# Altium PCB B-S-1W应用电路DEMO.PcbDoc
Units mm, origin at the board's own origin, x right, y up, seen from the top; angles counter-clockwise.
Board outline 40 x 15.24 mm, 2 copper layers (Top Layer, Bottom Layer); 6 components, 5 nets, 18 pads, 0 vias.
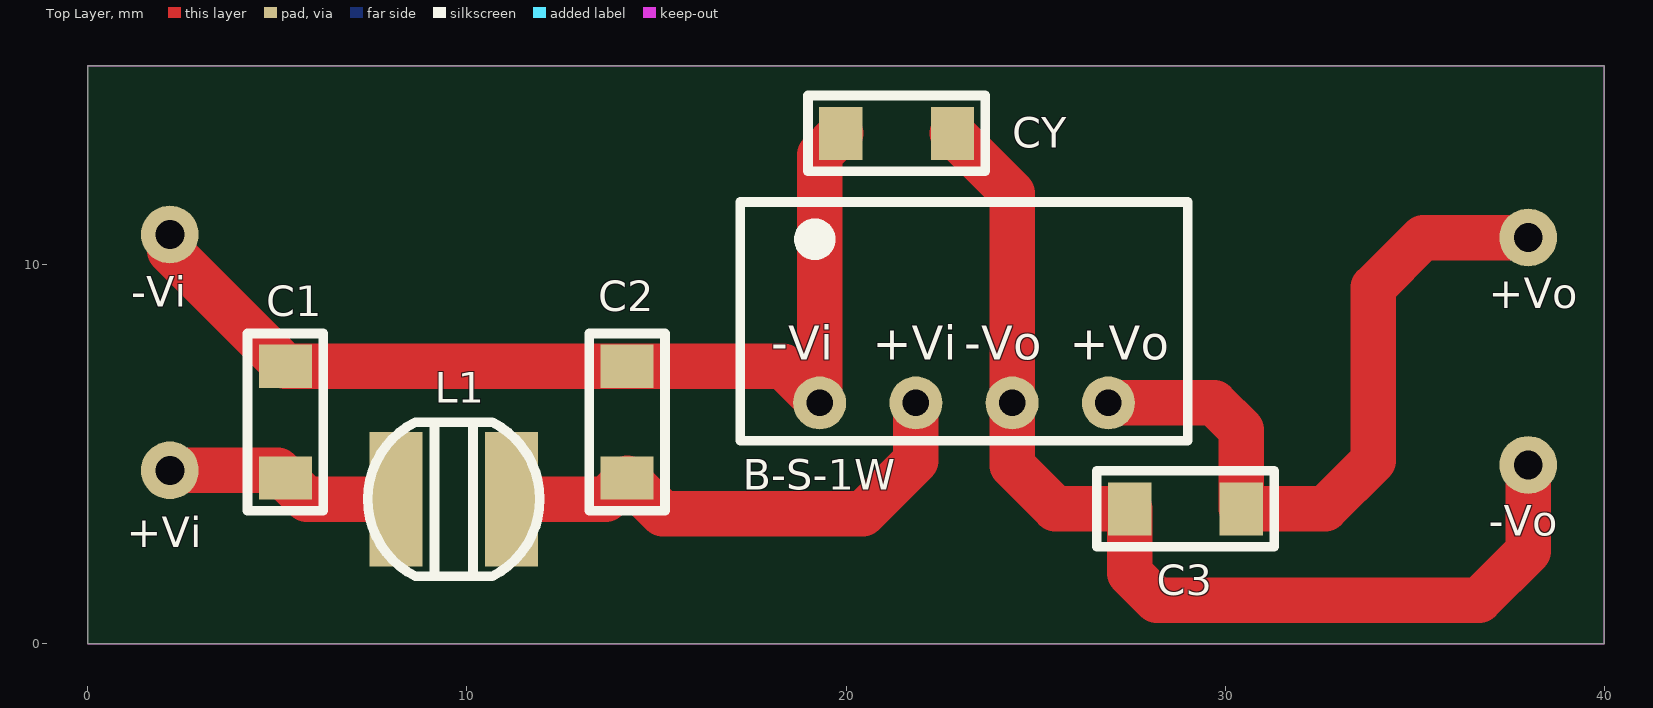
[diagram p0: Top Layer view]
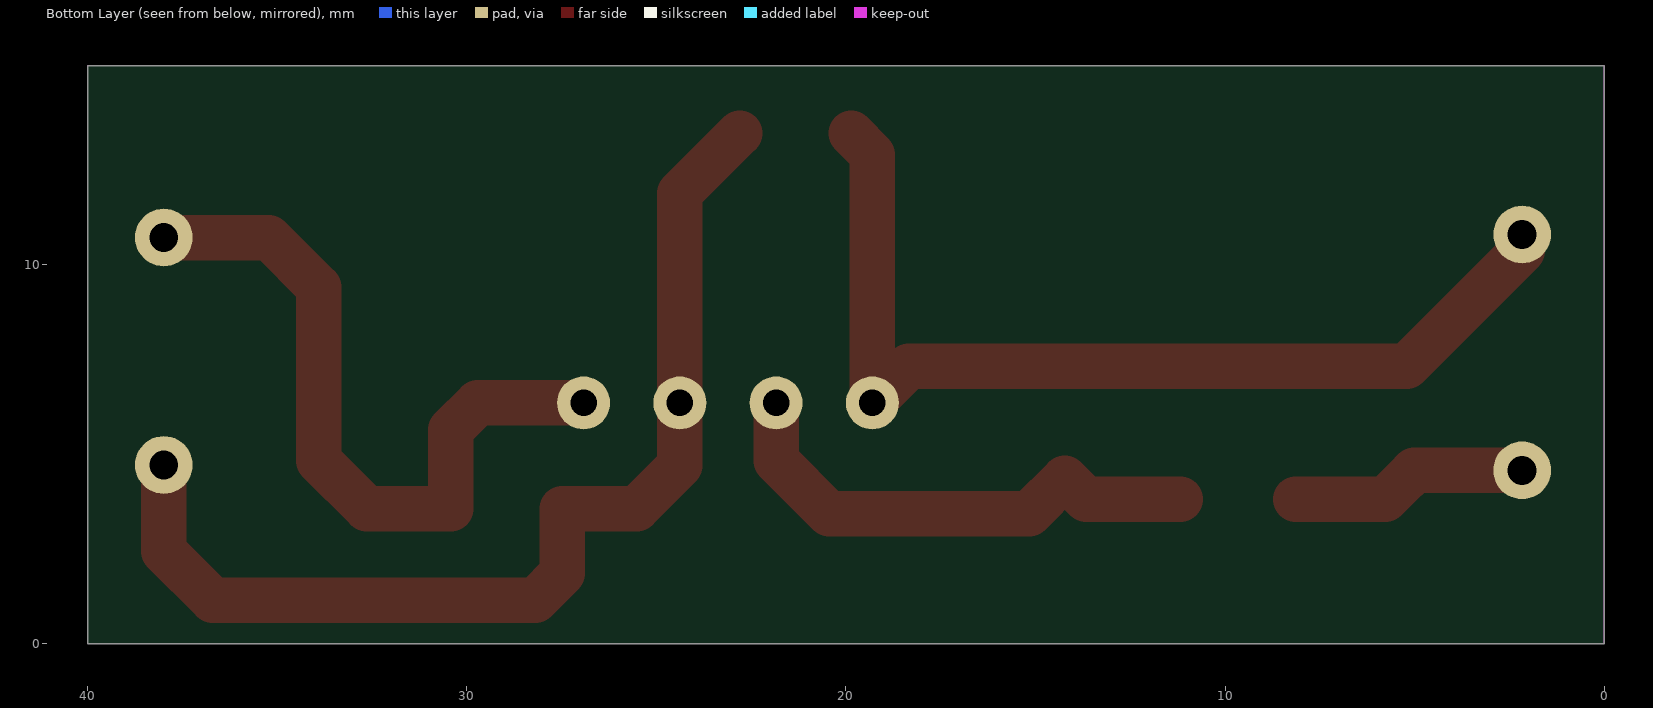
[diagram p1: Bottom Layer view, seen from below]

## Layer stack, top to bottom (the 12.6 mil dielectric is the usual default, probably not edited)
Top Layer: signal copper 0.0356
Dielectric: dielectric 0.32, FR-4, Dk 4.8
Bottom Layer: signal copper 0.0356

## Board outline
0,0 0,15.24 40,15.24 40,0

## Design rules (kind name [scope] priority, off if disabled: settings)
Clearance [All] p1: gap=0.254
PolygonConnect [All] p1: connectstyle=Relief reliefconductorwidth=0.254 reliefentries=4 polygonreliefangle="90 Angle"
RoutingVias [All] p1: holewidth=0.711 width=1.27 viastyle="Through Hole" minholewidth=0.711 minwidth=1.27 maxholewidth=0.711 maxwidth=1.27
SilkscreenOverComponentPads [All] p1: minsilkscreentomaskgap=0.254
SolderMaskExpansion [All] p1: expansion=0.102
TestPointUsage [All] p1: valid=0 allowmultiple=FALSE
Testpoint [All] p1: side=15 testpointundercomponent=TRUE minsize=1.016 maxsize=2.54 preferedsize=1.524 minholesize=0 maxholesize=1.016 preferedholesize=0.813 testpointgrid=0.025 style=1023 order=0123456789
Width [All] p1: maxlimit=2 minlimit=0.254 preferedwidth=0.254
23 further rules are at their usual default settings.

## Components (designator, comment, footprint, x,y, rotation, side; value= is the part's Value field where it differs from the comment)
B-S-1W "B-S-1W" B-S-1W 19.304,6.35 r0 top
C1 "" C1206 5.207,5.842 r90 top
C2 "" C1206 14.224,5.842 r90 top
C3 "" C1206 28.956,3.556 r0 top
CY "" C1206 21.336,13.462 r0 top
L1 "" CD43 9.652,3.81 r0 top

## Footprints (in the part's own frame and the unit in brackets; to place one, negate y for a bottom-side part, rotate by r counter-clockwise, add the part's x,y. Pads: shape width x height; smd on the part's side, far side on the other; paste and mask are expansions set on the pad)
B-S-1W [mm]
  round 1.4 hole 0.7: 1(0,0) 2(2.54,0) 3(5.08,0) 4(7.62,0)
  silkscreen extent -2.09,-1 9.71,5.3
C1206 [mil]
  rect 45x55 smd: 1(-58,0) 2(58,0)
  silkscreen extent -92,-39 92,39
CD43 [mil]
  rect 55x140 smd: 1(-60,0) 2(60,0)
  silkscreen extent -89,-80 89,80

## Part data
C1 C2 C3 CY: library part CAP
L1: library part INDUCTOR

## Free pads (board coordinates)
  round 1.524 hole 0.762: 0(2.159,4.572) 0(2.159,10.795) 1(38,4.714) 1(38,10.714)

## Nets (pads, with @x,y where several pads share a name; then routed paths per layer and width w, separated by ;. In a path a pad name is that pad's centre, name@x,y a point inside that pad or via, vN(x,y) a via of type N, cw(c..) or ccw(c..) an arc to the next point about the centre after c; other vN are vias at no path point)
NetB-S-1W_1: B-S-1W.1 C1.2 C2.2 CY.1 pad.0@2.159,10.795 | length 26.6
  Top Layer w1.2: pad.0@2.159,10.795 2.159,10.363 C1.2 C2.2 18.339,7.315 B-S-1W.1 19.304,12.903 CY.1
NetB-S-1W_2: B-S-1W.2 C2.1 L1.2 | length 13.4
  Top Layer w1.2: L1.2 13.665,3.81 C2.1 15.164,3.429 20.447,3.429 21.844,4.826 B-S-1W.2
NetB-S-1W_3: B-S-1W.3 C3.1 CY.2 pad.1@38,4.714 | length 28.3
  Top Layer w1.2: CY.2 24.384,11.887 B-S-1W.3 24.384,4.699 25.527,3.556 C3.1 27.483,1.854 28.194,1.143 36.703,1.143 38,2.44 pad.1@38,4.714
NetB-S-1W_4: B-S-1W.4 C3.2 pad.1@38,10.714 | length 19.1
  Top Layer w1.2: B-S-1W.4 29.718,6.35 30.429,5.639 C3.2 32.639,3.556 33.909,4.826 33.909,9.398 35.225,10.714 pad.1@38,10.714
NetC1_1: C1.1 L1.1 pad.0@2.159,4.572 | length 6.3
  Top Layer w1.2: pad.0@2.159,4.572 5.004,4.572 C1.1 5.766,3.81 L1.1

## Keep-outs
Keep-Out Layer:
  the board outline again, w0.025

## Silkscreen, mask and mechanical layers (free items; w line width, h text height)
Top Overlay:
  text "-Vi" at 1.143,8.89 h0.8
  text "+Vo" at 36.957,8.842 h0.8
  text "-Vo" at 36.957,2.842 h0.8
  text "+Vi" at 1.016,2.54 h0.8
